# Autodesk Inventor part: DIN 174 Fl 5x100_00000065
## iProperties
Created: 2006-03
Part Number: DIN 174 Fl 5x100_00000065
Material: Default
Document SubType Name: Modeling
Designer: Carlo
Stock Number: DIN 174 Fl 5x100
Mass: 1018.85 g
Surface Area: 4289.58 cm^2
Volume: 1018.85 cm^3
Density: 1 g/cm^3
G_L: 2037.896 mm
G_W: 5.000 mm
G_H: 100.000 mm
AFG_Item: 100 x 5
CSToolsMass: 1.0
CSToolsVolume: 1018849.0
CSToolsArea: 4290.0
Author: Carlo
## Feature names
1. AFG_Detailed_DIN 174 Fl 5x100_00000065 [Extrusion]
2. AFG_Simplified_DIN 174 Fl 5x100_00000065 [Extrusion]
3. AFG_StartExtrusion_1 [Extrusion]
4. AFG_StartExtrusion_2 [Extrusion]
5. AFG_EndExtrusion_1 [Extrusion]
6. AFG_EndExtrusion_2 [Extrusion]
